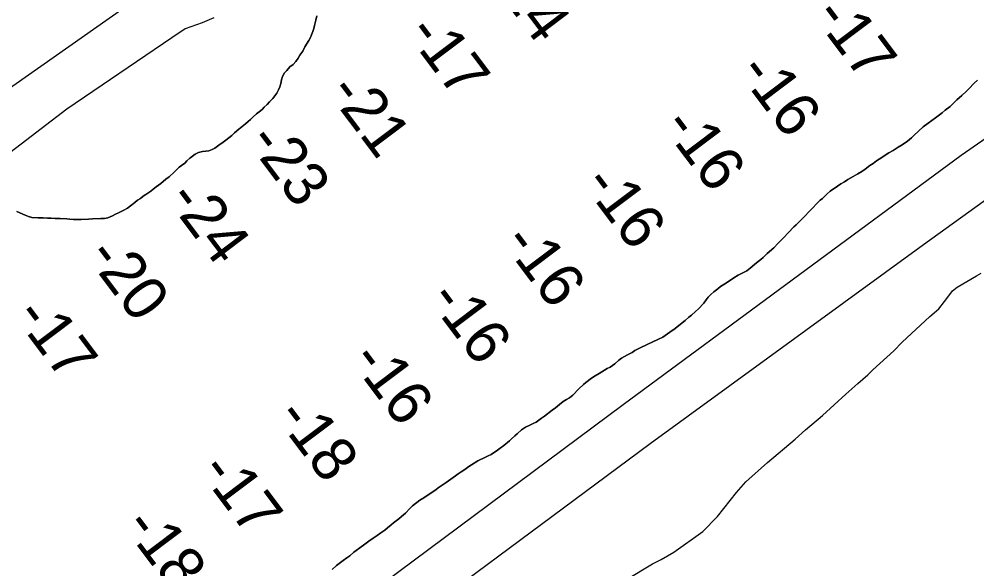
# Model space of a CAD drawing. Extents: x 3683613 to 3738215, y 469626 to 495384.
# Drawn here: x 3688948 to 3689919, y 487753 to 488310 of the extents above; entities that cross this region are included whole.
import ezdxf

# ---------------------------------------------------------------- set-up
doc = ezdxf.new("R2010")
doc.units = 0
for name, color, linetype in [('V-LEVE-TOET', 7, 'Continuous'), ('V-RIVR-JETY', 7, 'Continuous'), ('V-SITE-VEGE', 7, 'Continuous'), ('V-TOPO-SHOR', 7, 'Continuous'), ('V-TOPO-SPOT', 7, 'Continuous')]:
    doc.layers.add(name, color=color, linetype=linetype)

msp = doc.modelspace()

# ---------------------------------------------------------------- linework, layer by layer
at = {"layer": 'V-LEVE-TOET'}
for points in [[(3689105.7, 487581.59), (3689560.35, 487919.83), (3689902.51, 488172.2), (3690075.63, 488292.24), (3690116.38, 488319.54), (3690128.39, 488333.15), (3690136.19, 488341.66), (3690141.24, 488348.04), (3690147.56, 488354.64), (3690157.51, 488356.38), (3690157.51, 488356.38), (3690342.88, 488484.53), (3690354.02, 488502.16), (3690357.36, 488512.56), (3690362.82, 488523.17), (3690368.3, 488529.97), (3690375.49, 488532.12), (3690383.11, 488532.16), (3690387.57, 488530.7), (3690406.39, 488536.93), (3690461.26, 488578.48), (3690620.2, 488696.98)], [(3690509.27, 488548.84), (3690468.1, 488520.27), (3690449.12, 488503.45), (3690437.71, 488495.56), (3690426.1, 488487.25), (3690413.46, 488474.9), (3690407.98, 488468.73), (3690246.31, 488343.66), (3690138.23, 488267.54), (3690128.11, 488256.48), (3690121.57, 488251.37), (3690114.38, 488249.43), (3690103.59, 488247.26), (3690092.16, 488244.66), (3690085.4, 488241.45), (3690072.94, 488233.98), (3690048.25, 488213.96), (3689864.6, 488081.37), (3689587.44, 487879.92), (3689268.92, 487643.77)], [(3688803.07, 488145.2), (3689067.59, 488331.33)], [(3689145.42, 488311.36), (3689133.58, 488306.43), (3689116.24, 488300.21), (3689102.73, 488291.25), (3688996.31, 488218.75), (3688809.74, 488076.18)]]:
    msp.add_lwpolyline(points, dxfattribs=at)
at = {"layer": 'V-RIVR-JETY'}
for points in [[(3689547.03, 487957.7), (3689551.89, 487961.12), (3689555.89, 487964.73), (3689558.43, 487966.65), (3689564.55, 487970.07), (3689569.2, 487972.63), (3689572.16, 487974.34), (3689578.7, 487977.97), (3689582.51, 487979.68), (3689585.26, 487980.97), (3689589.48, 487982.89), (3689596.04, 487985.89), (3689600.26, 487988.03), (3689607.44, 487992.93), (3689612.72, 487996.77), (3689618.42, 488001.24), (3689622.85, 488004.86), (3689626.86, 488008.27), (3689629.39, 488010.4), (3689633.6, 488014.02), (3689636.56, 488016.79), (3689641.83, 488022.53), (3689644.14, 488025.72), (3689646.46, 488028.48), (3689648.99, 488031.25), (3689651.94, 488033.8), (3689655.95, 488037), (3689658.91, 488039.34), (3689665.03, 488043.18), (3689672.42, 488048.09), (3689676.86, 488050.65), (3689685.52, 488055.35), (3689688.9, 488057.91), (3689693.11, 488061.53), (3689697.12, 488064.73), (3689699.66, 488066.64), (3689702.19, 488068.77), (3689706.19, 488072.6), (3689712.73, 488078.56), (3689717.37, 488083.25), (3689722.64, 488088.57), (3689727.7, 488093.88), (3689732.97, 488099.63), (3689735.5, 488101.76), (3689738.87, 488105.16), (3689744.35, 488110.69), (3689748.57, 488115.37), (3689751.1, 488117.5), (3689757.42, 488124.31), (3689759.74, 488126.65), (3689762.06, 488128.57), (3689766.91, 488133.25), (3689770.08, 488135.81), (3689777.25, 488140.92), (3689780.63, 488143.27), (3689784.43, 488145.41), (3689787.81, 488147.75), (3689793.31, 488150.74), (3689797.95, 488153.52), (3689801.97, 488155.86), (3689805.56, 488158.21), (3689810.2, 488161.83), (3689813.36, 488163.97), (3689816.74, 488166.52), (3689822.23, 488169.94), (3689825.82, 488172.28), (3689829.41, 488174.63), (3689833.64, 488177.19), (3689838.92, 488180.39), (3689842.93, 488182.95), (3689848.21, 488186.37), (3689852.22, 488189.78), (3689854.75, 488192.12), (3689864.24, 488201.05), (3689869.3, 488204.68), (3689876.69, 488210.01), (3689883.45, 488215.12), (3689886.61, 488217.89), (3689891.46, 488221.52), (3689895.89, 488225.98), (3689898.21, 488228.32), (3689903.27, 488232.79), (3689908.12, 488237.27), (3689910.44, 488239.39), (3689915.92, 488245.14), (3689919.3, 488248.33)], [(3689265.44, 487752.64), (3689269.87, 487756.69), (3689276.41, 487761.8), (3689280.21, 487764.36), (3689283.16, 487766.7), (3689287.17, 487770.11), (3689289.49, 487772.03), (3689293.5, 487774.8), (3689298.57, 487778.42), (3689302.58, 487781.41), (3689306.8, 487784.6), (3689310.82, 487787.17), (3689314.62, 487789.72), (3689318.84, 487792.71), (3689321.37, 487794.84), (3689324.96, 487797.82), (3689327.49, 487799.95), (3689330.23, 487801.87), (3689332.76, 487804), (3689335.51, 487806.34), (3689339.51, 487809.75), (3689343.94, 487814.43), (3689346.68, 487817.19), (3689354.07, 487822.95), (3689358.08, 487825.3), (3689367.79, 487831.7), (3689370.33, 487833.4), (3689372.86, 487835.32), (3689377.93, 487838.94), (3689380.89, 487840.65), (3689390.39, 487847.47), (3689393.13, 487849.6), (3689395.87, 487851.52), (3689399.88, 487854.08), (3689403.9, 487856.86), (3689406.43, 487858.56), (3689412.98, 487862.62), (3689420.58, 487866.47), (3689423.33, 487867.96), (3689426.29, 487869.24), (3689432.83, 487873.51), (3689435.58, 487875.43), (3689439.17, 487878.2), (3689444.86, 487882.89), (3689447.18, 487885.02), (3689450.56, 487888), (3689452.88, 487890.13), (3689457.31, 487894.17), (3689461.32, 487896.73), (3689464.91, 487898.44), (3689469.14, 487900.58), (3689471.89, 487902.07), (3689477.59, 487906.12), (3689480.54, 487907.83), (3689488.35, 487914.01), (3689491.52, 487916.57), (3689495.52, 487919.98), (3689499.54, 487922.75), (3689502.7, 487924.88), (3689505.66, 487926.59), (3689509.25, 487929.36), (3689515.36, 487935.53), (3689520, 487940), (3689522.32, 487942.13), (3689528.23, 487946.39), (3689531.82, 487948.74), (3689535.83, 487951.08), (3689543.86, 487956.21), (3689547.03, 487957.7)]]:
    msp.add_lwpolyline(points, dxfattribs=at)
at = {"layer": 'V-SITE-VEGE'}
msp.add_lwpolyline([(3689563.48, 487742.62), (3689589.97, 487758.54), (3689598.56, 487762.89), (3689611.45, 487770.12), (3689640.78, 487791.08), (3689655.78, 487806.22), (3689675.05, 487830.72), (3689684.33, 487841.53), (3689706.49, 487861.01), (3689734.38, 487884.83), (3689745.1, 487894.21), (3689762.26, 487908.64), (3689785.85, 487930.29), (3689798, 487941.11), (3689808.01, 487949.77), (3689813.01, 487954.82), (3689834.45, 487974.3), (3689843.03, 487982.95), (3689870.9, 488008.92), (3689880.2, 488016.86), (3689885.9, 488024.07), (3689892.33, 488032.71), (3689893.75, 488034.87), (3689898.76, 488038.48), (3689918.09, 488050.06), (3689923.1, 488052.95)], dxfattribs=at)
at = {"layer": 'V-TOPO-SHOR'}
for points in [[(3689249.91, 488313.43), (3689248.66, 488309.19), (3689247.41, 488303.68), (3689246.58, 488300.5), (3689245.75, 488297.53), (3689244.49, 488294.35), (3689243.23, 488291.59), (3689241.55, 488288.61), (3689237.56, 488282.03), (3689235.46, 488277.78), (3689232.51, 488273.53), (3689230.83, 488270.56), (3689228.52, 488267.16), (3689225.78, 488264.18), (3689222.4, 488261.62), (3689219.24, 488258.22), (3689217.13, 488255.67), (3689214.82, 488252.06), (3689213.99, 488248.67), (3689213.37, 488244.85), (3689212.12, 488241.67), (3689210.86, 488238.48), (3689209.39, 488235.09), (3689205.18, 488229.56), (3689201.81, 488226.37), (3689199.28, 488223.61), (3689196.54, 488221.05), (3689194.22, 488218.71), (3689191.27, 488216.37), (3689188.73, 488214.03), (3689185.36, 488211.04), (3689182.62, 488208.49), (3689180.09, 488206.36), (3689177.34, 488204.02), (3689170.8, 488198.69), (3689166.37, 488194.86), (3689163.63, 488192.3), (3689160.47, 488189.96), (3689157.72, 488187.41), (3689154.98, 488185.49), (3689150.33, 488182.29), (3689146.54, 488179.3), (3689143.79, 488178.02), (3689140.41, 488176.73), (3689137.23, 488176.3), (3689134.06, 488176.07), (3689129.82, 488174.99), (3689126.65, 488173.49), (3689123.91, 488171.36), (3689120.95, 488169.44), (3689118.21, 488166.68), (3689115.89, 488164.34), (3689112.73, 488161.99), (3689110.41, 488160.08), (3689107.88, 488157.73), (3689105.14, 488154.97), (3689100.28, 488150.5), (3689096.91, 488147.94)], [(3689170.8, 488198.69), (3689177.34, 488204.02), (3689180.09, 488206.36), (3689182.62, 488208.49), (3689185.36, 488211.04), (3689188.73, 488214.03), (3689191.27, 488216.37), (3689194.22, 488218.71), (3689196.54, 488221.05), (3689199.28, 488223.61), (3689201.81, 488226.37), (3689205.18, 488229.56), (3689209.39, 488235.09), (3689210.86, 488238.48), (3689212.12, 488241.67), (3689213.37, 488244.85), (3689213.99, 488248.67), (3689214.82, 488252.06), (3689217.13, 488255.67), (3689219.24, 488258.22), (3689222.4, 488261.62), (3689225.78, 488264.18), (3689228.52, 488267.16), (3689230.83, 488270.56), (3689232.51, 488273.53), (3689235.46, 488277.78), (3689237.56, 488282.03), (3689241.55, 488288.61), (3689243.23, 488291.59), (3689244.49, 488294.35), (3689245.75, 488297.53), (3689246.58, 488300.5), (3689247.41, 488303.68), (3689248.66, 488309.19), (3689249.91, 488313.43)], [(3689547.03, 487957.7), (3689551.89, 487961.12), (3689555.89, 487964.73), (3689558.43, 487966.65), (3689564.55, 487970.07), (3689569.2, 487972.63), (3689572.16, 487974.34), (3689578.7, 487977.97), (3689582.51, 487979.68), (3689585.26, 487980.97), (3689589.48, 487982.89), (3689596.04, 487985.89), (3689600.26, 487988.03), (3689607.44, 487992.93), (3689612.72, 487996.77), (3689618.42, 488001.24), (3689622.85, 488004.86), (3689626.86, 488008.27), (3689629.39, 488010.4), (3689633.6, 488014.02), (3689636.56, 488016.79), (3689641.83, 488022.53), (3689644.14, 488025.72), (3689646.46, 488028.48), (3689648.99, 488031.25), (3689651.94, 488033.8), (3689655.95, 488037), (3689658.91, 488039.34), (3689665.03, 488043.18), (3689672.42, 488048.09), (3689676.86, 488050.65), (3689685.52, 488055.35), (3689688.9, 488057.91), (3689693.11, 488061.53), (3689697.12, 488064.73), (3689699.66, 488066.64), (3689702.19, 488068.77), (3689706.19, 488072.6), (3689712.73, 488078.56), (3689717.37, 488083.25), (3689722.64, 488088.57), (3689727.7, 488093.88), (3689732.97, 488099.63), (3689735.5, 488101.76), (3689738.87, 488105.16), (3689744.35, 488110.69), (3689748.57, 488115.37), (3689751.1, 488117.5), (3689757.42, 488124.31), (3689759.74, 488126.65), (3689762.06, 488128.57), (3689766.91, 488133.25), (3689770.08, 488135.81), (3689777.25, 488140.92), (3689780.63, 488143.27), (3689784.43, 488145.41), (3689787.81, 488147.75), (3689793.31, 488150.74), (3689797.95, 488153.52), (3689801.97, 488155.86), (3689805.56, 488158.21), (3689810.2, 488161.83), (3689813.36, 488163.97), (3689816.74, 488166.52), (3689822.23, 488169.94), (3689825.82, 488172.28), (3689829.41, 488174.63), (3689833.64, 488177.19), (3689838.92, 488180.39), (3689842.93, 488182.95), (3689848.21, 488186.37), (3689852.22, 488189.78), (3689854.75, 488192.12), (3689864.24, 488201.05), (3689869.3, 488204.68), (3689876.69, 488210.01), (3689883.45, 488215.12), (3689886.61, 488217.89), (3689891.46, 488221.52), (3689895.89, 488225.98), (3689898.21, 488228.32), (3689903.27, 488232.79), (3689908.12, 488237.27), (3689910.44, 488239.39), (3689915.92, 488245.14), (3689919.3, 488248.33)], [(3689919.3, 488248.33), (3689915.92, 488245.14), (3689910.44, 488239.39), (3689908.12, 488237.27), (3689903.27, 488232.79), (3689898.21, 488228.32), (3689895.89, 488225.98), (3689891.46, 488221.52), (3689886.61, 488217.89), (3689883.45, 488215.12), (3689876.69, 488210.01), (3689869.3, 488204.68), (3689864.24, 488201.05), (3689854.75, 488192.12), (3689852.22, 488189.78), (3689848.21, 488186.37), (3689842.93, 488182.95), (3689838.92, 488180.39)], [(3688945.83, 488115.25), (3688954.11, 488111.48), (3688957.5, 488110.23), (3688960.9, 488109.18), (3688967.47, 488108.79), (3688972.34, 488108.81), (3688977, 488108.62), (3688980.6, 488108.43), (3688984.62, 488108.23), (3688989.71, 488108.26), (3688996.28, 488107.86), (3688999.45, 488107.46), (3689003.06, 488107.26), (3689007.08, 488107.28), (3689010.89, 488107.09), (3689018.52, 488107.55), (3689022.54, 488107.78), (3689031.01, 488108.03), (3689034.61, 488108.04), (3689038, 488108.69), (3689042.65, 488110.84), (3689045.6, 488112.54), (3689048.77, 488114.04), (3689054.27, 488116.61), (3689057.86, 488118.74), (3689061.03, 488120.87), (3689065.25, 488124.49), (3689068.2, 488126.63), (3689070.95, 488128.33), (3689073.9, 488130.68), (3689076.65, 488132.6), (3689081.5, 488136.01), (3689084.03, 488137.93), (3689086.99, 488140.27), (3689091.63, 488143.68), (3689096.91, 488147.94), (3689100.28, 488150.5), (3689105.14, 488154.97), (3689107.88, 488157.73), (3689110.41, 488160.08), (3689112.73, 488161.99), (3689115.89, 488164.34), (3689118.21, 488166.68), (3689120.95, 488169.44), (3689123.91, 488171.36), (3689126.65, 488173.49), (3689129.82, 488174.99), (3689134.06, 488176.07), (3689137.23, 488176.3), (3689140.41, 488176.73), (3689143.79, 488178.02), (3689146.54, 488179.3), (3689150.33, 488182.29), (3689154.98, 488185.49), (3689157.72, 488187.41), (3689160.47, 488189.96), (3689163.63, 488192.3), (3689166.37, 488194.86), (3689170.8, 488198.69)], [(3689838.92, 488180.39), (3689833.64, 488177.19), (3689829.41, 488174.63), (3689825.82, 488172.28), (3689822.23, 488169.94), (3689816.74, 488166.52), (3689813.36, 488163.97), (3689810.2, 488161.83), (3689805.56, 488158.21), (3689801.97, 488155.86), (3689797.95, 488153.52), (3689793.31, 488150.74), (3689787.81, 488147.75), (3689784.43, 488145.41), (3689780.63, 488143.27), (3689777.25, 488140.92), (3689770.08, 488135.81), (3689766.91, 488133.25), (3689762.06, 488128.57), (3689759.74, 488126.65), (3689757.42, 488124.31), (3689751.1, 488117.5), (3689748.57, 488115.37), (3689744.35, 488110.69), (3689738.87, 488105.16), (3689735.5, 488101.76), (3689732.97, 488099.63), (3689727.7, 488093.88), (3689722.64, 488088.57), (3689717.37, 488083.25), (3689712.73, 488078.56), (3689706.19, 488072.6), (3689702.19, 488068.77), (3689699.66, 488066.64), (3689697.12, 488064.73), (3689693.11, 488061.53), (3689688.9, 488057.91), (3689685.52, 488055.35), (3689676.86, 488050.65), (3689672.42, 488048.09), (3689665.03, 488043.18), (3689658.91, 488039.34), (3689655.95, 488037), (3689651.94, 488033.8), (3689648.99, 488031.25), (3689646.46, 488028.48), (3689644.14, 488025.72), (3689641.83, 488022.53), (3689636.56, 488016.79), (3689633.6, 488014.02), (3689629.39, 488010.4), (3689626.86, 488008.27), (3689622.85, 488004.86), (3689618.42, 488001.24), (3689612.72, 487996.77), (3689607.44, 487992.93), (3689600.26, 487988.03), (3689596.04, 487985.89), (3689589.48, 487982.89), (3689585.26, 487980.97), (3689582.51, 487979.68), (3689578.7, 487977.97), (3689572.16, 487974.34), (3689569.2, 487972.63), (3689564.55, 487970.07), (3689558.43, 487966.65), (3689555.89, 487964.73), (3689551.89, 487961.12), (3689547.03, 487957.7), (3689543.86, 487956.21), (3689535.83, 487951.08), (3689531.82, 487948.74), (3689528.23, 487946.39), (3689522.32, 487942.13), (3689520, 487940), (3689515.36, 487935.53), (3689509.25, 487929.36), (3689505.66, 487926.59), (3689502.7, 487924.88), (3689499.54, 487922.75), (3689495.52, 487919.98), (3689491.52, 487916.57), (3689488.35, 487914.01), (3689480.54, 487907.83), (3689477.59, 487906.12), (3689471.89, 487902.07), (3689469.14, 487900.58), (3689464.91, 487898.44), (3689461.32, 487896.73), (3689457.31, 487894.17), (3689452.88, 487890.13), (3689450.56, 487888), (3689447.18, 487885.02), (3689444.86, 487882.89), (3689439.17, 487878.2), (3689435.58, 487875.43), (3689432.83, 487873.51), (3689426.29, 487869.24), (3689423.33, 487867.96), (3689420.58, 487866.47), (3689412.98, 487862.62)], [(3689096.91, 488147.94), (3689091.63, 488143.68), (3689086.99, 488140.27), (3689084.03, 488137.93), (3689081.5, 488136.01), (3689076.65, 488132.6), (3689073.9, 488130.68), (3689070.95, 488128.33), (3689068.2, 488126.63), (3689065.25, 488124.49), (3689061.03, 488120.87), (3689057.86, 488118.74), (3689054.27, 488116.61), (3689048.77, 488114.04), (3689045.6, 488112.54), (3689042.65, 488110.84), (3689038, 488108.69), (3689034.61, 488108.04), (3689031.01, 488108.03), (3689022.54, 488107.78), (3689018.52, 488107.55), (3689010.89, 488107.09), (3689007.08, 488107.28), (3689003.06, 488107.26), (3688999.45, 488107.46), (3688996.28, 488107.86), (3688989.71, 488108.26), (3688984.62, 488108.23), (3688980.6, 488108.43), (3688977, 488108.62), (3688972.34, 488108.81), (3688967.47, 488108.79), (3688960.9, 488109.18), (3688957.5, 488110.23), (3688954.11, 488111.48), (3688945.83, 488115.25)], [(3689265.44, 487752.64), (3689269.87, 487756.69), (3689276.41, 487761.8), (3689280.21, 487764.36), (3689283.16, 487766.7), (3689287.17, 487770.11), (3689289.49, 487772.03), (3689293.5, 487774.8), (3689298.57, 487778.42), (3689302.58, 487781.41), (3689306.8, 487784.6), (3689310.82, 487787.17), (3689314.62, 487789.72), (3689318.84, 487792.71), (3689321.37, 487794.84), (3689324.96, 487797.82), (3689327.49, 487799.95), (3689330.23, 487801.87), (3689332.76, 487804), (3689335.51, 487806.34), (3689339.51, 487809.75), (3689343.94, 487814.43), (3689346.68, 487817.19), (3689354.07, 487822.95), (3689358.08, 487825.3), (3689367.79, 487831.7), (3689370.33, 487833.4), (3689372.86, 487835.32), (3689377.93, 487838.94), (3689380.89, 487840.65), (3689390.39, 487847.47), (3689393.13, 487849.6), (3689395.87, 487851.52), (3689399.88, 487854.08), (3689403.9, 487856.86), (3689406.43, 487858.56), (3689412.98, 487862.62), (3689420.58, 487866.47), (3689423.33, 487867.96), (3689426.29, 487869.24), (3689432.83, 487873.51), (3689435.58, 487875.43), (3689439.17, 487878.2), (3689444.86, 487882.89), (3689447.18, 487885.02), (3689450.56, 487888), (3689452.88, 487890.13), (3689457.31, 487894.17), (3689461.32, 487896.73), (3689464.91, 487898.44), (3689469.14, 487900.58), (3689471.89, 487902.07), (3689477.59, 487906.12), (3689480.54, 487907.83), (3689488.35, 487914.01), (3689491.52, 487916.57), (3689495.52, 487919.98), (3689499.54, 487922.75), (3689502.7, 487924.88), (3689505.66, 487926.59), (3689509.25, 487929.36), (3689515.36, 487935.53), (3689520, 487940), (3689522.32, 487942.13), (3689528.23, 487946.39), (3689531.82, 487948.74), (3689535.83, 487951.08), (3689543.86, 487956.21), (3689547.03, 487957.7)], [(3689412.98, 487862.62), (3689406.43, 487858.56), (3689403.9, 487856.86), (3689399.88, 487854.08), (3689395.87, 487851.52), (3689393.13, 487849.6), (3689390.39, 487847.47), (3689380.89, 487840.65), (3689377.93, 487838.94), (3689372.86, 487835.32), (3689370.33, 487833.4), (3689367.79, 487831.7), (3689358.08, 487825.3), (3689354.07, 487822.95), (3689346.68, 487817.19), (3689343.94, 487814.43), (3689339.51, 487809.75), (3689335.51, 487806.34), (3689332.76, 487804), (3689330.23, 487801.87), (3689327.49, 487799.95), (3689324.96, 487797.82), (3689321.37, 487794.84), (3689318.84, 487792.71), (3689314.62, 487789.72), (3689310.82, 487787.17), (3689306.8, 487784.6), (3689302.58, 487781.41), (3689298.57, 487778.42), (3689293.5, 487774.8), (3689289.49, 487772.03), (3689287.17, 487770.11), (3689283.16, 487766.7), (3689280.21, 487764.36), (3689276.41, 487761.8), (3689269.87, 487756.69), (3689265.44, 487752.64)]]:
    msp.add_lwpolyline(points, dxfattribs=at)

# ---------------------------------------------------------------- texts
at = {"layer": 'V-TOPO-SPOT'}
for s, p in [('-14', (3689421.69, 488352.42)), ('-17', (3689751.92, 488313.37)), ('-17', (3689339.6, 488295.83)), ('-16', (3689675.45, 488256.64)), ('-21', (3689259.81, 488236.09)), ('-16', (3689598.8, 488201.71)), ('-23', (3689178.21, 488186.2)), ('-16', (3689518.19, 488143.18)), ('-24', (3689096.86, 488127.67)), ('-16', (3689436.73, 488084.01)), ('-20', (3689015.01, 488070.09)), ('-16', (3689361.71, 488026.45)), ('-17', (3688942.04, 488009.32)), ('-16', (3689282.73, 487964.72)), ('-18', (3689206.83, 487907.43)), ('-17', (3689129.66, 487852.35)), ('-18', (3689052.72, 487796.51))]:
    msp.add_text(s, height=45, rotation=306.93473, dxfattribs=at).set_placement(p)

doc.saveas('drawing.dxf')
